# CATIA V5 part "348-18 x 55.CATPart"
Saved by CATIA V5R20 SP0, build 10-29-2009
Part number: 348-18 x 55
Definition: NONE
Nomenclature: 348-18 x 55
Source: Unknown
Description: 348-18 x 55
Bounding box of the stored display mesh (mm): x 0 to 55, y -14 to 14, z -14 to 14
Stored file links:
  C:\Users\Utente\Desktop\IO LAVORO\3D X SITO CF\X SITO\3D files 348\348-18 x 55.CATPart
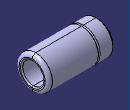
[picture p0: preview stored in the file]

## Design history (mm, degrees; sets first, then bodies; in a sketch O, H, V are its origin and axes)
Body1 "348-18 x 55" (main body)
  Solid1: solid without history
